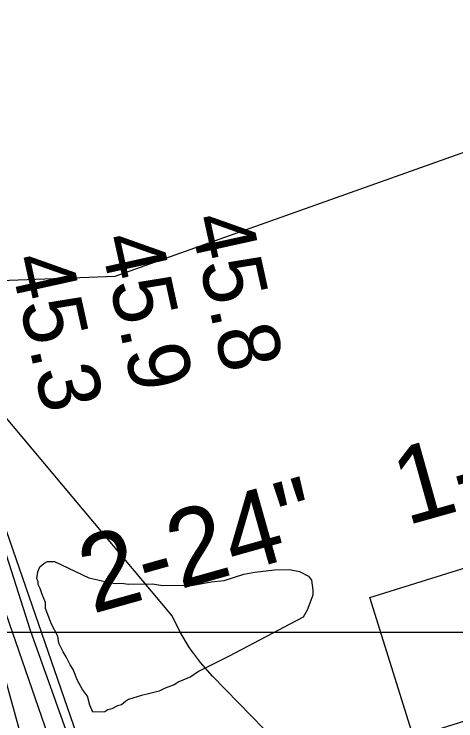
# Model space of a CAD drawing. Extents: x 3250478 to 3288318, y 788638 to 816472.
# Drawn here: x 3276767 to 3277247, y 806041 to 806808 of the extents above; entities that cross this region are included whole.
import ezdxf

# ---------------------------------------------------------------- set-up
doc = ezdxf.new("R2010")
doc.units = 0
for name, color, linetype in [('V-GRID-MAJR', 7, 'Continuous'), ('V-RIVR-RANG', 7, 'Continuous'), ('V-ROAD-CNTR', 7, 'Continuous'), ('V-SITE-OTLN', 7, 'Continuous'), ('V-SITE-VEGE', 7, 'Continuous'), ('V-TOPO-MINR', 7, 'Continuous'), ('V-UTIL-IDEN', 7, 'Continuous'), ('V-UTIL-LINE', 7, 'Continuous')]:
    doc.layers.add(name, color=color, linetype=linetype)

msp = doc.modelspace()

# ---------------------------------------------------------------- linework, layer by layer
at = {"layer": 'V-GRID-MAJR'}
msp.add_spline([(3254645.228, 806146.921), (3259882.848, 806143.493), (3265120.469, 806140.826), (3270358.09, 806138.922), (3275595.711, 806137.779), (3280833.333, 806137.398), (3286070.954, 806137.779), (3286070.955, 806137.779)], degree=3, dxfattribs=at)
at = {"layer": 'V-ROAD-CNTR'}
for points in [[(3277083.890139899, 805079.4572104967), (3277070.427617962, 805139.6743687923), (3277059.553345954, 805198.3359492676), (3277040.7312496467, 805262.5401107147), (3276996.9284975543, 805459.5112281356), (3276933.083676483, 805719.4833770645), (3276895.4507845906, 805872.5472212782), (3276842.9751199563, 806005.5873302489), (3276755.9660173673, 806257.095184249), (3276706.7598643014, 806455.3626837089), (3276649.069225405, 806623.2769519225), (3276569.8461540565, 806767.3349395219), (3276526.656532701, 806844.7290697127)], [(3277054.4418601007, 805073.6767895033), (3277041.030382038, 805133.6656312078), (3277030.334654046, 805191.3640507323), (3277011.6627503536, 805255.0558892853), (3276967.7155024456, 805452.6767718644), (3276903.950323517, 805712.3246229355), (3276866.8012154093, 805863.4207787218), (3276814.832880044, 805995.1746697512), (3276727.173982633, 806248.5608157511), (3276677.960135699, 806446.859316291), (3276621.5367745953, 806611.0850480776), (3276543.6038459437, 806752.7970604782), (3276499.963467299, 806830.9989302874)], [(3276535.7158913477, 806810.2223522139), (3276624.5537136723, 806657.4216578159), (3276665.261632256, 806587.405797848), (3276691.71957934, 806454.7180632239), (3276738.148486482, 806285.233402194), (3276784.8243931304, 806139.811693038), (3276839.993282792, 805985.6600013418), (3276906.808149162, 805760.5414515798), (3276954.3210541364, 805580.8668109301)]]:
    msp.add_lwpolyline(points, dxfattribs=at)
at = {"layer": 'V-SITE-OTLN'}
msp.add_lwpolyline([(3277153.875, 806175.3150000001), (3277387.179, 806247.954), (3277413.088, 806164.737), (3277296.4420000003, 806128.42), (3277317.694, 806060.162), (3277201.036, 806023.841)], close=True, dxfattribs=at)
at = {"layer": 'V-SITE-VEGE'}
msp.add_lwpolyline([(3277001.066, 806111.6020000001), (3276967.853, 806094.859), (3276959.303, 806089.3200000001), (3276946.431, 806083.71), (3276941.086, 806080.382), (3276931.419, 806076.987), (3276924.995, 806073.64), (3276912.088, 806070.191), (3276905.629, 806069.006), (3276891.659, 806064.459), (3276888.4560000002, 806062.245), (3276884.188, 806058.936), (3276879.887, 806057.787), (3276873.463, 806054.442), (3276869.16, 806053.291), (3276865.955, 806051.079), (3276852.997, 806050.868), (3276849.636, 806058.3740000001), (3276847.316, 806068.057), (3276841.795, 806075.528), (3276836.238, 806085.158), (3276831.727, 806096.9670000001), (3276828.399, 806102.312), (3276823.938, 806110.881), (3276820.612, 806116.23), (3276816.133, 806125.876), (3276814.931, 806133.417), (3276808.242, 806146.27), (3276801.482, 806163.441), (3276801.377, 806169.921), (3276797.9960000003, 806178.506), (3276795.733, 806184.951), (3276793.503, 806189.233), (3276793.45, 806192.473), (3276792.3170000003, 806195.6950000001), (3276793.275, 806203.272), (3276795.346, 806208.706), (3276799.612, 806212.015), (3276803.896, 806214.246), (3276811.4560000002, 806214.366), (3276848.467, 806196.608), (3276858.222, 806194.607), (3276870.153, 806191.562), (3276877.7290000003, 806190.603), (3276884.207, 806190.71), (3276891.782, 806189.752), (3276917.7, 806190.1730000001), (3276928.531, 806188.191), (3276962.006, 806188.734), (3276981.39, 806192.289), (3276995.411, 806193.598), (3277016.903, 806200.4280000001), (3277028.744, 806202.781), (3277050.306, 806205.292), (3277066.503, 806205.556), (3277077.335, 806203.571), (3277087.143, 806198.331), (3277090.453, 806194.063), (3277091.708, 806183.282), (3277091.796, 806177.883), (3277088.697, 806169.192), (3277085.58, 806161.581), (3277081.384, 806153.9500000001)], close=True, dxfattribs=at)
at = {"layer": 'V-TOPO-MINR'}
for points in [[(3276784.6690255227, 805990.7311672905), (3276683.5132090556, 806355.8300936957), (3276677.1345508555, 806378.1949341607), (3276670.5320149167, 806400.4916374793), (3276663.593662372, 806422.6861350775), (3276656.431432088, 806444.812495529), (3276618.0422593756, 806560.4228062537), (3276601.644330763, 806606.7107438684), (3276584.0437516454, 806652.5088787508), (3276564.6391967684, 806697.5723095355), (3276544.031991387, 806742.145937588), (3276522.990821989, 806786.560199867), (3276502.577439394, 806831.2532829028)], [(3277202.0500000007, 805683.74), (3277082.906669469, 805966.3217032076), (3277074.128056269, 805984.2434584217), (3277064.11261441, 806001.3441800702), (3277052.241929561, 806017.2133513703), (3277039.1344160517, 806032.261489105), (3277039.06100556, 806032.3367349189), (3277025.0296177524, 806046.7078613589), (3277010.9908697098, 806061.071788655), (3276996.9410813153, 806075.4249172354), (3276982.8839326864, 806089.7708466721), (3276969.773489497, 806104.7467057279), (3276957.8961210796, 806120.5452775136), (3276947.868364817, 806137.5779183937), (3276939.0736833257, 806155.4332720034), (3276723.2800000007, 806412.3200000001), (3276582.568623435, 806818.4114401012)]]:
    msp.add_lwpolyline(points, dxfattribs=at)
at = {"layer": 'V-UTIL-LINE'}
msp.add_lwpolyline([(3275141.896, 805984.118), (3276656.77, 806515.544), (3276877.286, 806524.156), (3277840.19, 806866.721), (3278355.395, 807030.15), (3278608.833, 807099.192), (3280710.704, 807649.4890000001), (3281180.975, 807775.1190000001), (3281615.44, 807894.738)], dxfattribs=at)

# ---------------------------------------------------------------- texts
at = {"layer": 'V-RIVR-RANG'}
for s, p in [('45.8', (3276957.741563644, 806586.4188245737)), ('45.9', (3276860.091658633, 806564.8703929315)), ('45.3', (3276762.554563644, 806542.8058245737))]:
    msp.add_text(s, height=67, rotation=282.4583257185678, dxfattribs=at).set_placement(p)
at = {"layer": 'V-UTIL-IDEN'}
msp.add_text('2-24"   1-18" GAS PIPELINES', height=82.99983200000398, rotation=15.70253410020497, dxfattribs=at).set_placement((3276852.4280397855, 806157.3799276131))

doc.saveas('drawing.dxf')
